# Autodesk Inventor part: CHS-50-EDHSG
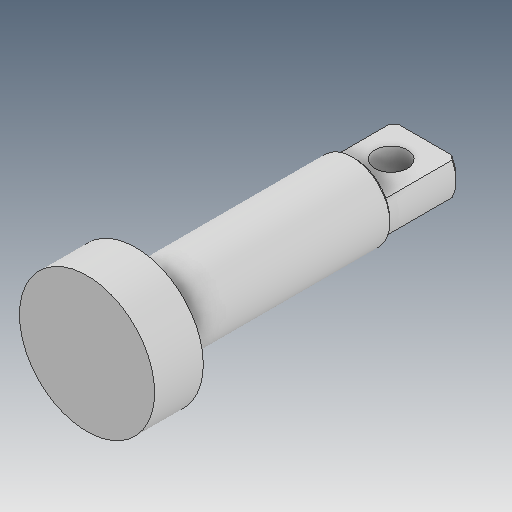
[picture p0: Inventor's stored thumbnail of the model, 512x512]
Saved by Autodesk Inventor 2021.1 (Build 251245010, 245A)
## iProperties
Created: 2019-04
Part Number: CHS-50-EDHSG
Material: Ogólny
Document SubType Name: Modeling
Designer: user
Density: 1 g/cm^3
Appearance: Domyślna
Author: user
Revision Number: ÈÎºÎ
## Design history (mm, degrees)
feature "ÊäÈë1"
node "Bryła1"
